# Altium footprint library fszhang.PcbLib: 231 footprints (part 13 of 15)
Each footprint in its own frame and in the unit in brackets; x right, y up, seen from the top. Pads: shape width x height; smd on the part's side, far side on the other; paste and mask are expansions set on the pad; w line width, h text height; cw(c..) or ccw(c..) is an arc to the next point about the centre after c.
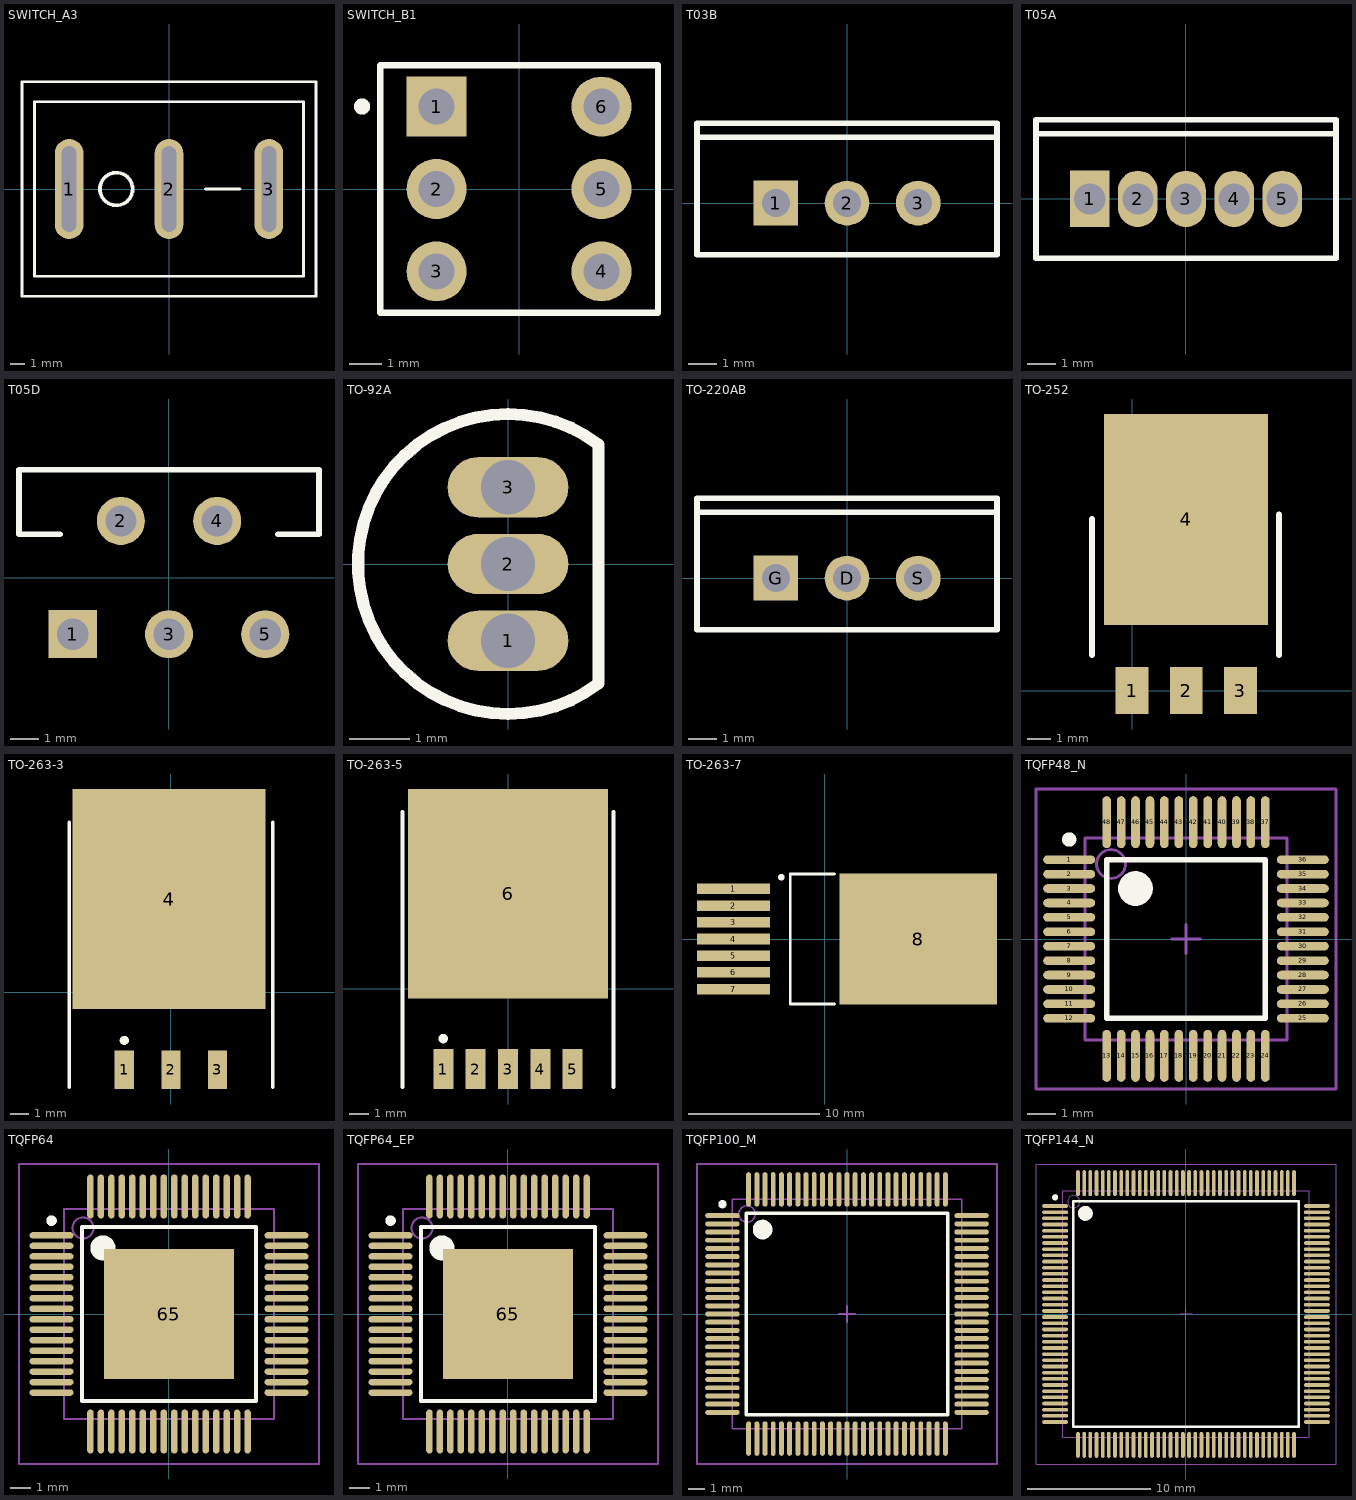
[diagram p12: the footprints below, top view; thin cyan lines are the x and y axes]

## SWITCH_A3 [mm] "单刀单掷开关"
height 9
pads (3):
  oval 2x7 hole 1 slot 6 at 90 deg: 1(-6.985,0) 2(0,0) 3(6.985,0)
Top Overlay:
  circle w0.254: c-3.683,0 r1.143
  lines w0.2: 2.54,0 4.953,0 ; -10.287,-7.493 10.287,-7.493 10.287,7.493 -10.287,7.493 -10.287,-7.493 ; -9.398,-6.096 -9.398,6.096 9.398,6.096 9.398,-6.096 -9.398,-6.096

## SWITCH_B1 [mm] "单刀"
height 1.75
pads (6):
  rect 1.85x1.85 hole 1.1: 1(-2.54,2.54)
  round 1.85 hole 1.1: 2(-2.54,0) 3(-2.54,-2.54) 4(2.54,-2.54) 5(2.54,0) 6(2.54,2.54)
Top Overlay:
  circle w0.25: c-4.836,2.541 r0.125
  lines w0.2: -4.28,-3.81 4.28,-3.81 4.28,3.81 -4.28,3.81 -4.28,-3.81

## T03B [mm] "TO, Thru-Hole, Vertical, Heatsink Mounted; 3 In-Line Leads; Pitch 2.54 mm"
height 19.4
pads (3):
  rect 1.6x1.6 hole 1: 1(-2.54,0)
  round 1.6 hole 1: 2(0,0) 3(2.54,0)
Top Overlay:
  lines w0.2: -5.35,2.35 5.35,2.35 ; -5.35,-1.85 5.35,-1.85 5.35,2.85 -5.35,2.85 -5.35,-1.85

## T05A [mm] "TO, Thru-Hole, Vertical, Heatsink Mounted; 5 In-Line Leads; Pitch 1.70 mm"
height 15.3
pads (5):
  rect 1.4x2 hole 1.1: 1(-3.4,0)
  oval 1.4x2 hole 1.1: 2(-1.7,0) 3(0,0) 4(1.7,0) 5(3.4,0)
Top Overlay:
  lines w0.2: -5.3,2.3 5.3,2.3 ; -5.3,-2.1 -5.3,2.8 5.3,2.8 5.3,-2.1 -5.3,-2.1

## T05D [mm]
height 21.1
pads (5):
  rect 1.7x1.7 hole 1.1: 1(-3.4,-2)
  round 1.7 hole 1.1: 2(-1.7,2) 3(0,-2) 4(1.7,2) 5(3.4,-2)
Top Overlay:
  lines w0.2: -3.854,1.53 -5.3,1.53 -5.3,3.81 5.3,3.81 5.3,1.53 3.854,1.53

## TO-92A [mm]
height 6.86
pads (3):
  oval 2x1 hole 0.9: 1(0,-1.27) 2(0,0) 3(0,1.27)
Top Overlay:
  lines w0.2: 1.5,-1.98 cw(c0,0) 1.5,1.98 1.5,-1.98

## TO-220AB [mm] "TO, Thru-Hole, Vertical, Heatsink Mounted; 3 In-Line Leads; Pitch 2.54 mm"
height 19.3
pads (3):
  round 1.6 hole 1: D(0,0) S(2.54,0)
  rect 1.6x1.6 hole 1: G(-2.54,0)
Top Overlay:
  lines w0.2: -5.35,2.35 5.35,2.35 ; -5.35,-1.85 -5.35,2.85 5.35,2.85 5.35,-1.85 -5.35,-1.85
3D body: height 4, standoff 0.6, extent -5.334,2.286 5.334,2.794
3D body: height 0.6, standoff 0, extent 1.778,-0.381 3.302,0.508
3D body: height 0.6, standoff 0, extent -0.762,-0.381 0.762,0.508
3D body: height 0.6, standoff 0, extent -3.302,-0.381 -1.778,0.508
3D body: height 3.6, standoff 0.6, extent -5.334,-1.778 5.334,2.286

## TO-252 [mm]
pads (4):
  rect 1.4x2 smd: 1(0,0) 2(2.311,0) 3(4.623,0)
  rect 7x9 smd: 4(2.3,7.3)
Top Overlay:
  lines w0.254: -1.716,1.524 -1.716,7.315 ; 6.261,1.524 6.261,7.515

## TO-263-3 [mm] "LM2940/LM1086"
height 4.65
pads (4):
  rect 1.05x2.1 smd: 1(-2.54,-4.225) 2(0,-4.225) 3(2.54,-4.225)
  rect 10.5x12 smd: 4(-0.104,5.08)
Top Overlay:
  circle w0.25: c-2.54,-2.625 r0.125
  lines w0.2: -5.55,-5.175 -5.55,9.275 ; 5.55,-5.175 5.55,9.275
3D body: height 1.6, standoff 0, extent -5.334,-1.778 5.334,9.271
3D body: height 0.8, standoff 0, extent -3.048,-4.699 -2.032,-1.778
3D body: height 0.8, standoff 0, extent -0.508,-4.699 0.508,-1.778
3D body: height 0.8, standoff 0, extent 2.032,-4.699 3.048,-1.778

## TO-263-5 [mm] "贴片LM2596"
height 4.65
pads (6):
  rect 1.05x2.1 smd: 1(-3.4,-4.225) 2(-1.7,-4.225) 3(0,-4.225) 4(1.7,-4.225) 5(3.4,-4.225)
  rect 10.5x11 smd: 6(0,4.987)
Top Overlay:
  circle w0.25: c-3.4,-2.625 r0.125
  lines w0.2: -5.55,-5.175 -5.55,9.275 ; 5.55,-5.175 5.55,9.275
3D body: height 3, standoff 0, extent -5.334,-0.508 5.334,9.271
3D body: height 1, standoff 0, extent -5.334,9.271 5.334,10.287
3D body: height 0.6, standoff 0, extent -3.81,-4.699 -2.921,-0.508
3D body: height 0.6, standoff 0, extent -2.159,-4.699 -1.27,-0.508
3D body: height 0.6, standoff 0, extent -0.508,-4.699 0.381,-0.508
3D body: height 0.6, standoff 0, extent 1.27,-4.699 2.159,-0.508
3D body: height 0.6, standoff 0, extent 2.921,-4.699 3.81,-0.508

## TO-263-7 [mm] "TO, 8-Pads,7970"
height 4.4
pads (8):
  rect 5.55x0.8 smd: 1(-6.943,3.81) 2(-6.943,2.54) 3(-6.943,1.27) 4(-6.943,0) 5(-6.943,-1.27) 6(-6.943,-2.54) 7(-6.943,-3.81)
  rect 12x10 smd: 8(7.112,0)
Top Overlay:
  circle w0.25: c-3.3,4.699 r0.125
  lines w0.2: 0.75,-4.95 -2.625,-4.95 -2.625,4.95 0.75,4.95

## TQFP48_N [mm] "Thin QFP, 48-Leads, Body 7x7mm, Pitch 0.5mm, IPC Medium Density"
height 1.6
pads (48):
  oval 1.8x0.3 smd: 1(-4.05,2.75) 2(-4.05,2.25) 3(-4.05,1.75) 4(-4.05,1.25) 5(-4.05,0.75) 6(-4.05,0.25) 7(-4.05,-0.25) 8(-4.05,-0.75) 9(-4.05,-1.25) 10(-4.05,-1.75) 11(-4.05,-2.25) 12(-4.05,-2.75) 25(4.05,-2.75) 26(4.05,-2.25) 27(4.05,-1.75) 28(4.05,-1.25) 29(4.05,-0.75) 30(4.05,-0.25) 31(4.05,0.25) 32(4.05,0.75) 33(4.05,1.25) 34(4.05,1.75) 35(4.05,2.25) 36(4.05,2.75)
  oval 0.3x1.8 smd: 13(-2.75,-4.05) 14(-2.25,-4.05) 15(-1.75,-4.05) 16(-1.25,-4.05) 17(-0.75,-4.05) 18(-0.25,-4.05) 19(0.25,-4.05) 20(0.75,-4.05) 21(1.25,-4.05) 22(1.75,-4.05) 23(2.25,-4.05) 24(2.75,-4.05) 37(2.75,4.05) 38(2.25,4.05) 39(1.75,4.05) 40(1.25,4.05) 41(0.75,4.05) 42(0.25,4.05) 43(-0.25,4.05) 44(-0.75,4.05) 45(-1.25,4.05) 46(-1.75,4.05) 47(-2.25,4.05) 48(-2.75,4.05)
Top Overlay:
  circle w0.25: c-4.05,3.45 r0.125
  circle w0.6: c-1.75,1.75 r0.3
  lines w0.2: -2.75,-2.75 -2.75,2.75 2.75,2.75 2.75,-2.75 -2.75,-2.75
Mechanical 13:
  circle w0.1: c-2.6,2.6 r0.5
  lines w0.1: -3.5,-3.5 -3.5,3.5 3.5,3.5 3.5,-3.5 -3.5,-3.5
Mechanical 15:
  lines w0.1: -0.5,0 0.5,0 ; 0,-0.5 0,0.5 ; -5.2,-5.2 -5.2,5.2 5.2,5.2 5.2,-5.2 -5.2,-5.2
3D body: height 1.6, standoff 0, extent -3.5,-3.5 3.5,3.5

## TQFP64 [mm]
height 1.2
pads (65):
  oval 2.1x0.3 smd: 1(-5.6,3.75) 2(-5.6,3.25) 3(-5.6,2.75) 4(-5.6,2.25) 5(-5.6,1.75) 6(-5.6,1.25) 7(-5.6,0.75) 8(-5.6,0.25) 9(-5.6,-0.25) 10(-5.6,-0.75) 11(-5.6,-1.25) 12(-5.6,-1.75) 13(-5.6,-2.25) 14(-5.6,-2.75) 15(-5.6,-3.25) 16(-5.6,-3.75) 33(5.6,-3.75) 34(5.6,-3.25) 35(5.6,-2.75) 36(5.6,-2.25) 37(5.6,-1.75) 38(5.6,-1.25) 39(5.6,-0.75) 40(5.6,-0.25) 41(5.6,0.25) 42(5.6,0.75) 43(5.6,1.25) 44(5.6,1.75) 45(5.6,2.25) 46(5.6,2.75) 47(5.6,3.25) 48(5.6,3.75)
  oval 0.3x2.1 smd: 17(-3.75,-5.6) 18(-3.25,-5.6) 19(-2.75,-5.6) 20(-2.25,-5.6) 21(-1.75,-5.6) 22(-1.25,-5.6) 23(-0.75,-5.6) 24(-0.25,-5.6) 25(0.25,-5.6) 26(0.75,-5.6) 27(1.25,-5.6) 28(1.75,-5.6) 29(2.25,-5.6) 30(2.75,-5.6) 31(3.25,-5.6) 32(3.75,-5.6) 49(3.75,5.6) 50(3.25,5.6) 51(2.75,5.6) 52(2.25,5.6) 53(1.75,5.6) 54(1.25,5.6) 55(0.75,5.6) 56(0.25,5.6) 57(-0.25,5.6) 58(-0.75,5.6) 59(-1.25,5.6) 60(-1.75,5.6) 61(-2.25,5.6) 62(-2.75,5.6) 63(-3.25,5.6) 64(-3.75,5.6)
  rect 6.2x6.2 smd: 65(0,0)
Top Overlay:
  circle w0.6: c-3.15,3.15 r0.3
  circle w0.25: c-5.6,4.45 r0.125
  lines w0.2: -4.15,-4.15 4.15,-4.15 4.15,4.15 -4.15,4.15 -4.15,-4.15
Mechanical 13:
  circle w0.1: c-4.1,4.1 r0.5
  lines w0.1: -5,-5 5,-5 5,5 -5,5 -5,-5
Mechanical 15:
  lines w0.1: -0.5,0 0.5,0 ; 0,-0.5 0,0.5 ; -7.15,-7.15 7.15,-7.15 7.15,7.15 -7.15,7.15 -7.15,-7.15
3D body: height 1.2, standoff 0, extent -5,-5 5,5

## TQFP64_EP [mm]
height 1.2
pads (65):
  oval 2.1x0.3 smd: 1(-5.6,3.75) 2(-5.6,3.25) 3(-5.6,2.75) 4(-5.6,2.25) 5(-5.6,1.75) 6(-5.6,1.25) 7(-5.6,0.75) 8(-5.6,0.25) 9(-5.6,-0.25) 10(-5.6,-0.75) 11(-5.6,-1.25) 12(-5.6,-1.75) 13(-5.6,-2.25) 14(-5.6,-2.75) 15(-5.6,-3.25) 16(-5.6,-3.75) 33(5.6,-3.75) 34(5.6,-3.25) 35(5.6,-2.75) 36(5.6,-2.25) 37(5.6,-1.75) 38(5.6,-1.25) 39(5.6,-0.75) 40(5.6,-0.25) 41(5.6,0.25) 42(5.6,0.75) 43(5.6,1.25) 44(5.6,1.75) 45(5.6,2.25) 46(5.6,2.75) 47(5.6,3.25) 48(5.6,3.75)
  oval 0.3x2.1 smd: 17(-3.75,-5.6) 18(-3.25,-5.6) 19(-2.75,-5.6) 20(-2.25,-5.6) 21(-1.75,-5.6) 22(-1.25,-5.6) 23(-0.75,-5.6) 24(-0.25,-5.6) 25(0.25,-5.6) 26(0.75,-5.6) 27(1.25,-5.6) 28(1.75,-5.6) 29(2.25,-5.6) 30(2.75,-5.6) 31(3.25,-5.6) 32(3.75,-5.6) 49(3.75,5.6) 50(3.25,5.6) 51(2.75,5.6) 52(2.25,5.6) 53(1.75,5.6) 54(1.25,5.6) 55(0.75,5.6) 56(0.25,5.6) 57(-0.25,5.6) 58(-0.75,5.6) 59(-1.25,5.6) 60(-1.75,5.6) 61(-2.25,5.6) 62(-2.75,5.6) 63(-3.25,5.6) 64(-3.75,5.6)
  rect 6.2x6.2 smd: 65(0,0)
Top Overlay:
  circle w0.6: c-3.15,3.15 r0.3
  circle w0.25: c-5.6,4.45 r0.125
  lines w0.2: -4.15,-4.15 4.15,-4.15 4.15,4.15 -4.15,4.15 -4.15,-4.15
Mechanical 13:
  circle w0.1: c-4.1,4.1 r0.5
  lines w0.1: -5,-5 5,-5 5,5 -5,5 -5,-5
Mechanical 15:
  lines w0.1: -0.5,0 0.5,0 ; 0,-0.5 0,0.5 ; -7.15,-7.15 7.15,-7.15 7.15,7.15 -7.15,7.15 -7.15,-7.15
3D body: height 1.2, standoff 0, extent -5,-5 5,5

## TQFP100_M [mm] "Thin QFP, 100-Leads, Body 14x14mm, Pitch 0.5mm, IPC Low Density"
height 1.2
pads (100):
  oval 2.1x0.3 smd: 1(-7.6,6) 2(-7.6,5.5) 3(-7.6,5) 4(-7.6,4.5) 5(-7.6,4) 6(-7.6,3.5) 7(-7.6,3) 8(-7.6,2.5) 9(-7.6,2) 10(-7.6,1.5) 11(-7.6,1) 12(-7.6,0.5) 13(-7.6,0) 14(-7.6,-0.5) 15(-7.6,-1) 16(-7.6,-1.5) 17(-7.6,-2) 18(-7.6,-2.5) 19(-7.6,-3) 20(-7.6,-3.5) 21(-7.6,-4) 22(-7.6,-4.5) 23(-7.6,-5) 24(-7.6,-5.5) 25(-7.6,-6) 51(7.6,-6) 52(7.6,-5.5) 53(7.6,-5) 54(7.6,-4.5) 55(7.6,-4) 56(7.6,-3.5) 57(7.6,-3) 58(7.6,-2.5) 59(7.6,-2) 60(7.6,-1.5) 61(7.6,-1) 62(7.6,-0.5) 63(7.6,0) 64(7.6,0.5) 65(7.6,1) 66(7.6,1.5) 67(7.6,2) 68(7.6,2.5) 69(7.6,3) 70(7.6,3.5) 71(7.6,4) 72(7.6,4.5) 73(7.6,5) 74(7.6,5.5) 75(7.6,6)
  oval 0.3x2.1 smd: 26(-6,-7.6) 27(-5.5,-7.6) 28(-5,-7.6) 29(-4.5,-7.6) 30(-4,-7.6) 31(-3.5,-7.6) 32(-3,-7.6) 33(-2.5,-7.6) 34(-2,-7.6) 35(-1.5,-7.6) 36(-1,-7.6) 37(-0.5,-7.6) 38(0,-7.6) 39(0.5,-7.6) 40(1,-7.6) 41(1.5,-7.6) 42(2,-7.6) 43(2.5,-7.6) 44(3,-7.6) 45(3.5,-7.6) 46(4,-7.6) 47(4.5,-7.6) 48(5,-7.6) 49(5.5,-7.6) 50(6,-7.6) 76(6,7.6) 77(5.5,7.6) 78(5,7.6) 79(4.5,7.6) 80(4,7.6) 81(3.5,7.6) 82(3,7.6) 83(2.5,7.6) 84(2,7.6) 85(1.5,7.6) 86(1,7.6) 87(0.5,7.6) 88(0,7.6) 89(-0.5,7.6) 90(-1,7.6) 91(-1.5,7.6) 92(-2,7.6) 93(-2.5,7.6) 94(-3,7.6) 95(-3.5,7.6) 96(-4,7.6) 97(-4.5,7.6) 98(-5,7.6) 99(-5.5,7.6) 100(-6,7.6)
Top Overlay:
  circle w0.6: c-5.15,5.15 r0.3
  circle w0.25: c-7.6,6.7 r0.125
  lines w0.2: -6.15,-6.15 6.15,-6.15 6.15,6.15 -6.15,6.15 -6.15,-6.15
Mechanical 13:
  circle w0.1: c-6.1,6.1 r0.5
  lines w0.1: -7,-7 7,-7 7,7 -7,7 -7,-7
Mechanical 15:
  lines w0.1: -0.5,0 0.5,0 ; 0,-0.5 0,0.5 ; -9.15,-9.15 9.15,-9.15 9.15,9.15 -9.15,9.15 -9.15,-9.15
3D body: height 1.2, standoff 0, extent -7,-7 7,7

## TQFP144_N [mm] "TTM32V103ZET6"
height 1.6
pads (144):
  oval 2.1x0.3 smd: 1(-10.6,8.75) 2(-10.6,8.25) 3(-10.6,7.75) 4(-10.6,7.25) 5(-10.6,6.75) 6(-10.6,6.25) 7(-10.6,5.75) 8(-10.6,5.25) 9(-10.6,4.75) 10(-10.6,4.25) 11(-10.6,3.75) 12(-10.6,3.25) 13(-10.6,2.75) 14(-10.6,2.25) 15(-10.6,1.75) 16(-10.6,1.25) 17(-10.6,0.75) 18(-10.6,0.25) 19(-10.6,-0.25) 20(-10.6,-0.75) 21(-10.6,-1.25) 22(-10.6,-1.75) 23(-10.6,-2.25) 24(-10.6,-2.75) 25(-10.6,-3.25) 26(-10.6,-3.75) 27(-10.6,-4.25) 28(-10.6,-4.75) 29(-10.6,-5.25) 30(-10.6,-5.75) 31(-10.6,-6.25) 32(-10.6,-6.75) 33(-10.6,-7.25) 34(-10.6,-7.75) 35(-10.6,-8.25) 36(-10.6,-8.75) 73(10.6,-8.75) 74(10.6,-8.25) 75(10.6,-7.75) 76(10.6,-7.25) 77(10.6,-6.75) 78(10.6,-6.25) 79(10.6,-5.75) 80(10.6,-5.25) 81(10.6,-4.75) 82(10.6,-4.25) 83(10.6,-3.75) 84(10.6,-3.25) 85(10.6,-2.75) 86(10.6,-2.25) 87(10.6,-1.75) 88(10.6,-1.25) 89(10.6,-0.75) 90(10.6,-0.25) 91(10.6,0.25) 92(10.6,0.75) 93(10.6,1.25) 94(10.6,1.75) 95(10.6,2.25) 96(10.6,2.75) 97(10.6,3.25) 98(10.6,3.75) 99(10.6,4.25) 100(10.6,4.75) 101(10.6,5.25) 102(10.6,5.75) 103(10.6,6.25) 104(10.6,6.75) 105(10.6,7.25) 106(10.6,7.75) 107(10.6,8.25) 108(10.6,8.75)
  oval 0.3x2.1 smd: 37(-8.75,-10.6) 38(-8.25,-10.6) 39(-7.75,-10.6) 40(-7.25,-10.6) 41(-6.75,-10.6) 42(-6.25,-10.6) 43(-5.75,-10.6) 44(-5.25,-10.6) 45(-4.75,-10.6) 46(-4.25,-10.6) 47(-3.75,-10.6) 48(-3.25,-10.6) 49(-2.75,-10.6) 50(-2.25,-10.6) 51(-1.75,-10.6) 52(-1.25,-10.6) 53(-0.75,-10.6) 54(-0.25,-10.6) 55(0.25,-10.6) 56(0.75,-10.6) 57(1.25,-10.6) 58(1.75,-10.6) 59(2.25,-10.6) 60(2.75,-10.6) 61(3.25,-10.6) 62(3.75,-10.6) 63(4.25,-10.6) 64(4.75,-10.6) 65(5.25,-10.6) 66(5.75,-10.6) 67(6.25,-10.6) 68(6.75,-10.6) 69(7.25,-10.6) 70(7.75,-10.6) 71(8.25,-10.6) 72(8.75,-10.6) 109(8.75,10.6) 110(8.25,10.6) 111(7.75,10.6) 112(7.25,10.6) 113(6.75,10.6) 114(6.25,10.6) 115(5.75,10.6) 116(5.25,10.6) 117(4.75,10.6) 118(4.25,10.6) 119(3.75,10.6) 120(3.25,10.6) 121(2.75,10.6) 122(2.25,10.6) 123(1.75,10.6) 124(1.25,10.6) 125(0.75,10.6) 126(0.25,10.6) 127(-0.25,10.6) 128(-0.75,10.6) 129(-1.25,10.6) 130(-1.75,10.6) 131(-2.25,10.6) 132(-2.75,10.6) 133(-3.25,10.6) 134(-3.75,10.6) 135(-4.25,10.6) 136(-4.75,10.6) 137(-5.25,10.6) 138(-5.75,10.6) 139(-6.25,10.6) 140(-6.75,10.6) 141(-7.25,10.6) 142(-7.75,10.6) 143(-8.25,10.6) 144(-8.75,10.6)
Top Overlay:
  circle w0.25: c-10.6,9.45 r0.125
  circle w0.6: c-8.15,8.15 r0.3
  lines w0.2: -9.15,-9.15 -9.15,9.15 9.15,9.15 9.15,-9.15 -9.15,-9.15
Mechanical 13:
  circle w0.1: c-9.1,9.1 r0.5
  lines w0.1: -10,-10 -10,10 10,10 10,-10 -10,-10
Mechanical 15:
  lines w0.1: -0.5,0 0.5,0 ; 0,-0.5 0,0.5 ; -12.15,-12.15 -12.15,12.15 12.15,12.15 12.15,-12.15 -12.15,-12.15
3D body: height 1.6, standoff 0, extent -10,-10 10,10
